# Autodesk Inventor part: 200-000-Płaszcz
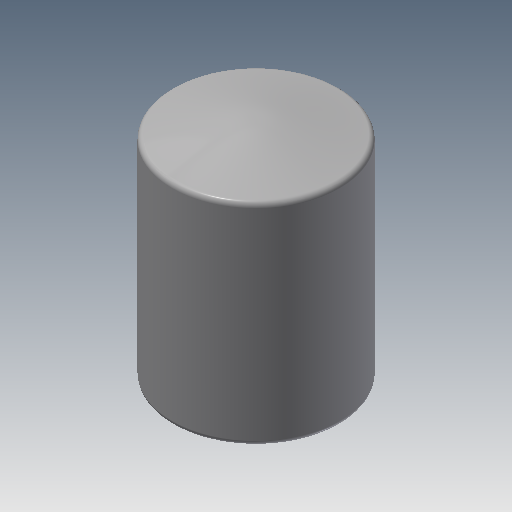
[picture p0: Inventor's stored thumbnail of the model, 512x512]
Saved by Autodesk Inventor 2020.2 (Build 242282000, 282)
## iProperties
Created: 2014-03
Part Number: 200-000-Płaszcz
Material: Stal
Document SubType Name: Modeling
Designer: F.Stasiak
Density: 7.85 g/cm^3
Appearance: Stal
Catalog Web Link: www.expertbooks.pl
Manager: www.cadconsulting.pl
Company: Fabian Stasiak CAD Consulting
Author: F.Stasiak
Subject: Zbiór ćwiczeń. Autodesk Inventor 2020. Kurs Professional
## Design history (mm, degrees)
sketch "Szkic1"
  geometry: L1 (800, -0.001)-(800, 2000); L2 (84.176, 2150)-(-84.176, 2150); L3 (0, 2150)-(0, -150.001); L4 (82.468, -150.001)-(-82.468, -150.001); L5 (0, 1000)-(800, 1000); L6 (882.898, 1985.383)-(717.102, 2014.617); L7 (240.924, -123.608)-(109.076, -145.159); L8 (881.215, 14.319)-(718.785, -14.321); A1 r 4878.813 centre (0, -2728.813) between (67.335, 2149.535) and (-67.335, 2149.535); A2 r 1750.164 centre (0, 1600.163) between (-65.927, -148.759) and (65.927, -148.759); A3 r 2243.83 centre (1189.637, 4209.741) between (733.887, 2012.683) and (866.464, 1989.306); A4 r 2153.773 centre (-172.429, 1991.183) between (122.171, -142.347) and (227.616, -125.112); A5 r 1644.522 centre (1085.568, -1619.539) between (865.149, 10.144) and (735.31, -12.75); 3 further points
  constraints: 16 end point, 12 midpoint, 5 centre point, 5 horizontal, 5 point on circle, 1 parallel, 1 point on line, 1 vertical, 14 other
  dimensions: "d1" = 800 distance of point (0, 0) L1.start; "d11" = 10 dimension on L2.start L2.end; "d12" = 10 dimension on L4.start L4.end; "d13" = 150 vertical distance of L1.end L3.start; "d14" = 150 vertical distance of L3.end L1.start (derived); "d15" = 350 diameter of point (175, 2135.045) L3; "d16" = 350 diameter of point (175, -134.383) L3; "d17" = 10 dimension on L6.start L6.end; "d18" = 10 dimension on L8.start L8.end; "d20" = 80 deg angle of L1 L8; "d21" = 80 deg angle of L6 L1; "d22" = 2300.00097 distance of L3.start L3.end
revolve "Obrót1" sketch "Szkic1" stored, may be unused: angle "d3" = 90 deg
fillet "Zaokrąglenie3" dims "d10" = 50
feature "Skorupa1" dims "d5" = 5
node "Bryła1"
